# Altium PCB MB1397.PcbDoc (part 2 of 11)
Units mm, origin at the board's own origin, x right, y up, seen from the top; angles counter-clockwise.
Board outline 118.24 x 172.86 mm, 6 copper layers (Top Layer, L2_GND, L3_VCC, L4_SIG, L5_GND, Bottom Layer), stack 1.631 mm thick; 819 components, 632 nets, 2875 pads, 1523 vias.
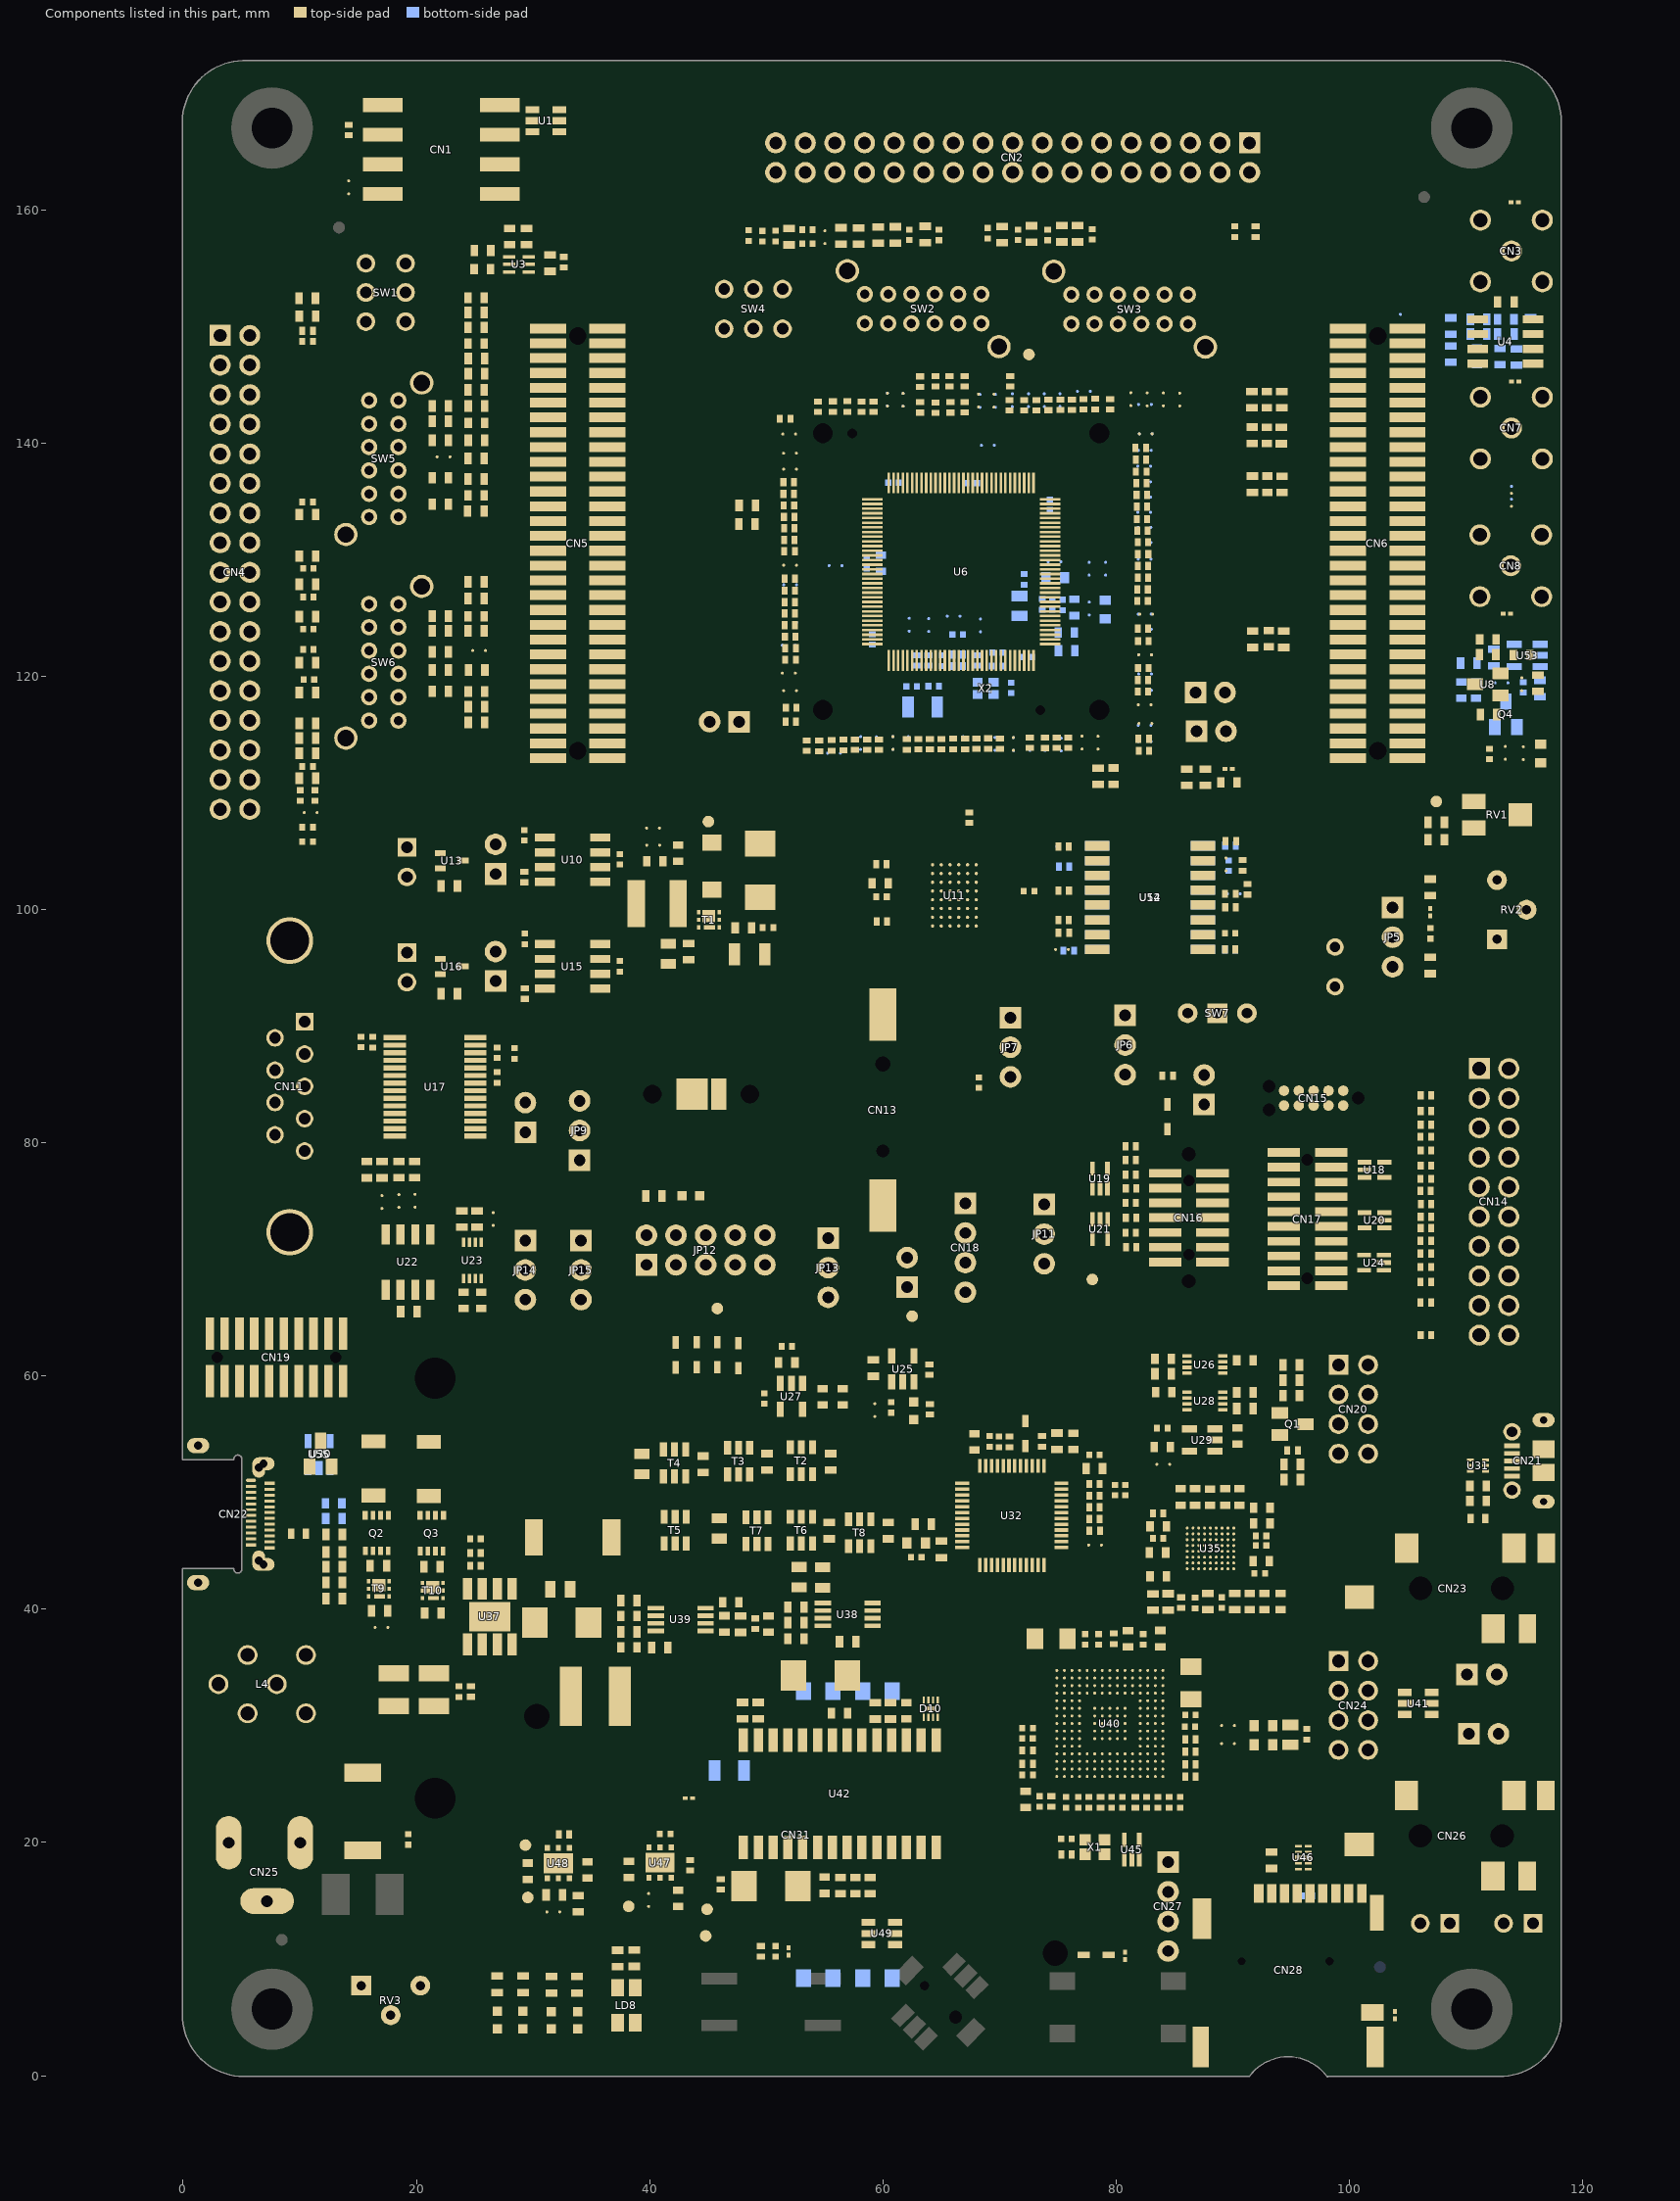
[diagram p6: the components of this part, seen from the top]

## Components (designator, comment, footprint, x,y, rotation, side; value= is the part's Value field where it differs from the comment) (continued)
HW3 "Logo" LOGO_ROHS 5.105,159.639 r0 top
HW4 "Logo" LOGO_MAIN_1 99.464,155.618 r0 top
HW5 "Logo" LOGO_CE 105.562,155.981 r0 top
HW7 "Comment" STICKER_25X9 41.176,60.325 r180 bottom
JP1 "Jumper_Header 2x1" CON_SAMTEC_TSW-102-07-G-S 46.406,116.098 r180 top
JP2 "Jumper_Header 2x1" CON_SAMTEC_TSW-102-07-G-S 26.782,104.314 r90 top
JP4 "Jumper_Header 2x1" CON_SAMTEC_TSW-102-07-G-S 26.782,95.124 r90 top
JP5 "Jumper_Header 3x1" CON_SAMTEC_TSW-103-07-F-S 103.701,97.627 r270 top
JP6 "Jumper_Header 3x1" CON_SAMTEC_TSW-103-07-F-S 80.772,88.377 r270 top
JP7 "Jumper_Header 3x1" CON_SAMTEC_TSW-103-07-F-S 70.924,88.187 r270 top
JP8 "Jumper_Header 2x1" CON_SAMTEC_TSW-102-07-G-S 87.538,84.54 r90 top
JP9 "Jumper_Header 3x1" CON_SAMTEC_TSW-103-07-F-S 33.995,81.05 r90 top
JP10 "Jumper_Header 2x1" CON_SAMTEC_TSW-102-07-G-S 29.337,82.169 r90 top
JP11 "Jumper_Header 3x1" CON_SAMTEC_TSW-103-07-F-S 73.83,72.162 r270 top
JP12 "Jumper_Header 5x2 Fitted 1-2" CON_SAMTEC_TSW-105-07-X-D 44.797,70.803 r0 top
JP13 "Jumper_Header 3x1" CON_SAMTEC_TSW-103-07-F-S 55.304,69.286 r270 top
JP14 "Jumper_Header 3x1" CON_SAMTEC_TSW-103-07-F-S 29.337,69.088 r270 top
JP15 "Jumper_Header 3x1" CON_SAMTEC_TSW-103-07-F-S 34.117,69.088 r270 top
JP16 "Jumper_Header 2x1" CON_SAMTEC_TSW-102-07-G-S 111.354,34.417 r0 top
JP17 "Jumper_Header 2x1" CON_SAMTEC_TSW-102-07-G-S 111.506,29.314 r0 top
JP18 "Jumper_Header 2x1" CON_SAMTEC_TSW-102-07-G-S 62.078,68.885 r90 top
L1 "BEAD" L0603 116.383,113.379 r90 top
L2 "Inductor" IND_POWER_CYNTEC_PSI054T 40.642,100.505 r180 top
L3 "BEAD" L0603 62.837,45.691 r180 top
L4 "BNX002-01" FIL_MURATA_BNX002-01 8.026,33.576 r180 top locked
L5 "INDUCTOR_POWER" IND_TDK_VLS6045EX-4R7M 35.331,32.537 r0 top
L6 "BEAD" L0603 92.634,30.023 r0 top
L7 "BEAD" L0603 92.634,28.385 r0 top
L8 "BEAD" L0603 74.778,128.44 r180 bottom
L9 "BEAD" L0603 79.052,125.705 r90 bottom
LD1 "LED_green" LED_0603_OSRAM_LG-Q396-PS-35_GREEN_1A2K_H0P4 26.924,4.766 r90 top
LD2 "LED_orange" LED_0603_OSRAM_LO-Q976-PS-25_ORANGE_1A2K_H0P8 29.143,4.766 r90 top
LD3 "LED_red" LED_0603_VISHAY_VLMS1300-GS08_RED_1A2K_H0P8 31.567,4.752 r90 top
LD4 "LED_blue" LED_0603_OSRAM_LB-Q39G-L2OO-35-1_BLUE_1A2K_H0P4 33.81,4.752 r90 top
LD5 "LED_white" LED_EVERLUCK_CWC12100_WHITE_1A2K 44.426,84.161 r0 top
LD6 "LED_green" LED_0603_OSRAM_LG-Q396-PS-35_GREEN_1A2K_H0P4 43.534,75.442 r0 top
LD7 "LED_red" LED_0603_VISHAY_VLMS1300-GS08_RED_1A2K_H0P8 62.637,57.028 r90 top
LD8 "LD_BICOLOR_CMS" LED_BI-GR_HSMF-A201-A00J1 38.006,6.05 r0 top
LPB1 "LPB-S01110101S" LIGHT_10MM-SQUARE-LIGHT-BAR_LUMEX_LPB-S01110101S-110945 44.416,84.149 r0 top
Q1 "BSN20" MOS_SOT23 95.123,55.88 r270 top
Q2 "STL9P3LLH6" MOS_POWERFLAT_3P3X3P3_P065 16.602,46.53 r0 top
Q3 "STL9P3LLH6" MOS_POWERFLAT_3P3X3P3_P065 21.308,46.529 r0 top
Q4 "9013-SOT23" NPN_SOT23 113.411,116.738 r180 bottom
R1 "Resistor" R0402 14.192,166.827 r90 top
R2 "Resistor" R0603 75.328,157.937 r90 top
R3 "Resistor" R0603 76.694,157.937 r270 top
R4 "Resistor" R0603 72.726,157.924 r90 top
R5 "Resistor" R0603 63.634,157.887 r270 top
R6 "Resistor" R0603 70.203,157.861 r90 top
R7 "Resistor" R0603 61.07,157.845 r270 top
R8 "Resistor" R0603 59.603,157.818 r90 top
R9 "Resistor" R0402 91.945,158.115 r270 top
R10 "Resistor" R0603 56.388,157.752 r270 top
R11 "Resistor" R0603 57.93,157.737 r90 top
R12 "Resistor" R0603 51.96,157.687 r270 top
R13 "Resistor" R0603 29.439,157.709 r270 top
R14 "Resistor" R0603 31.445,155.423 r90 top
R15 "Resistor" R0603 25.679,156.507 r0 top
R16 "Resistor" R0402 32.639,155.51 r90 top
R17 "Resistor" R0603 27.991,157.709 r270 top
R18 "Resistor" R0603 10.64,152.425 r0 top
R19 "Resistor" R0603 113.411,152.095 r0 top
R20 "Resistor" R0603 25.121,151.181 r180 top
R21 "Resistor" R0603 10.66,150.876 r180 top
R22 "Resistor" R0603 25.121,149.911 r0 top
R23 "Resistor" R0402 10.668,149.606 r0 top
R24 "Resistor" R0603 25.146,147.241 r0 top
R25 "Resistor" R0603 25.146,145.948 r180 top
R26 "Resistor" R0402 64.501,145.288 r270 top
R27 "Resistor" R0402 65.703,145.288 r90 top
R28 "Resistor" R0402 67.003,145.288 r90 top
R29 "Resistor" R0402 70.903,145.288 r90 top
R30 "Resistor" R0402 63.19,145.263 r270 top
R31 "Resistor" R0603 25.121,144.542 r180 top
R32 "Resistor" R0603 91.645,143.724 r270 top
R33 "Resistor" R0603 94.185,143.724 r270 top
R34 "Resistor" R0402 77.188,143.312 r90 top
R35 "Resistor" R0402 79.477,143.325 r90 top
R36 "Resistor" R0402 78.194,143.333 r90 top
R37 "Resistor" R0402 76.2,143.283 r90 top
R38 "Resistor" R0402 75.209,143.275 r90 top
R39 "Resistor" R0402 74.196,143.265 r90 top
R40 "Resistor" R0402 70.852,143.236 r90 top
R41 "Resistor" R0402 72.103,143.236 r90 top
R42 "Resistor" R0402 73.152,143.236 r90 top
R43 "Resistor" R0402 55.702,143.121 r90 top
R44 "Resistor" R0402 56.946,143.126 r270 top
R45 "Resistor" R0402 58.166,143.099 r270 top
R46 "Resistor" R0402 59.181,143.099 r270 top
R47 "Resistor" R0402 54.43,143.101 r270 top
R48 "Resistor" R0402 67.003,143.074 r90 top
R49 "Resistor" R0402 63.19,143.053 r270 top
R50 "Resistor" R0402 65.786,143.053 r90 top
R51 "Resistor" R0603 25.146,143.184 r180 top
R52 "Resistor" R0603 22.051,143.179 r0 top
R53 "Resistor" R0402 64.501,143.024 r90 top
R54 "Resistor" R0402 51.61,142.085 r0 top
R55 "Resistor" R0603 22.051,141.875 r0 top
R56 "Resistor" R0603 91.658,140.665 r90 top
R57 "Resistor" R0603 94.168,140.637 r90 top
R58 "Resistor" R0603 22.051,140.228 r0 top
R59 "Resistor" R0603 25.146,140.228 r0 top
R60 "Resistor" R0402 82.099,139.573 r180 top
R61 "Resistor" R0603 25.113,138.674 r0 top
R62 "Resistor" R0402 82.118,138.582 r180 top
R63 "Resistor" R0402 82.149,137.541 r180 top
R64 "Resistor" R0603 22.051,137.017 r0 top
R65 "Resistor" R0603 91.693,136.463 r90 top
R66 "Resistor" R0603 25.113,136.925 r0 top
R67 "Resistor" R0603 94.216,136.444 r90 top
R68 "Resistor" R0402 51.918,136.627 r180 top
R69 "Resistor" R0402 82.169,136.55 r180 top
R70 "Resistor" R0402 51.919,135.636 r180 top
R71 "Resistor" R0402 82.194,135.56 r180 top
R72 "Resistor" R0603 22.042,134.747 r0 top
R73 "Resistor" R0603 48.362,134.645 r180 top
R74 "Resistor" R0402 51.944,134.645 r180 top
R75 "Resistor" R0402 82.208,134.536 r180 top
R76 "Resistor" R0603 25.095,134.163 r180 top
R77 "Resistor" R0603 10.66,133.866 r0 top
R78 "Resistor" R0402 51.96,133.666 r180 top
R79 "Resistor" R0402 82.211,133.473 r180 top
R80 "Resistor" R0603 48.336,133.045 r180 top
R81 "Resistor" R0402 51.972,132.69 r180 top
R82 "Resistor" R0402 82.25,132.48 r180 top
R83 "Resistor" R0402 51.972,131.695 r180 top
R84 "Resistor" R0402 82.287,131.489 r180 top
R85 "Resistor" R0402 51.994,130.708 r180 top
R86 "Resistor" R0603 10.66,130.302 r180 top
R87 "Resistor" R0402 82.305,130.468 r0 top
R88 "Resistor" R0402 82.287,129.457 r0 top
R89 "Resistor" R0402 82.292,128.441 r0 top
R90 "Resistor" R0402 52.019,128.366 r180 top
R91 "Resistor" R0603 25.121,128.079 r0 top
R92 "Resistor" R0603 10.66,127.889 r180 top
R93 "Resistor" R0402 82.262,127.455 r0 top
R94 "Resistor" R0402 52.022,127.341 r180 top
R95 "Resistor" R0603 25.121,126.67 r0 top
R96 "Resistor" R0402 82.262,126.451 r0 top
R97 "Resistor" R0402 52.019,126.365 r180 top
R98 "Resistor" R0402 52.019,125.375 r180 top
R99 "Resistor" R0603 22.051,125.166 r0 top
R100 "Resistor" R0603 10.66,125.103 r180 top
R101 "Resistor" R0402 52.019,124.384 r180 top
R102 "Resistor" R0402 82.294,124.079 r0 top
R103 "Resistor" R0603 22.051,123.879 r0 top
R104 "Resistor" R0603 25.121,123.879 r180 top
R105 "Resistor" R0603 91.702,123.167 r270 top
R106 "Resistor" R0603 94.349,123.167 r270 top
R107 "Resistor" R0402 52.045,123.393 r180 top
R108 "Resistor" R0402 82.321,123.018 r0 top
R109 "Resistor" R0402 52.078,122.411 r0 top
R110 "Resistor" R0603 22.051,122.082 r0 top
R111 "Resistor" R0603 111.851,121.856 r180 top
R112 "Resistor" R0402 52.078,121.412 r180 top
R113 "Resistor" R0603 10.66,121.158 r0 top
R114 "Resistor" R0603 22.051,120.545 r0 top
R115 "Resistor" R0603 25.171,120.541 r180 top
R116 "Resistor" R0402 82.321,120.701 r180 top
R117 "Resistor" R0603 116.176,119.407 r90 top
R118 "Resistor" R0402 82.296,119.667 r180 top
R119 "Resistor" R0603 22.051,118.707 r0 top
R120 "Resistor" R0603 10.66,118.603 r0 top
R121 "Resistor" R0402 82.284,118.684 r180 top
R122 "Resistor" R0603 25.146,117.373 r0 top
R123 "Resistor" R0402 52.124,117.299 r0 top
R124 "Resistor" R0603 111.933,116.698 r0 top
R125 "Resistor" R0603 25.146,116.027 r0 top
R126 "Resistor" R0603 10.66,115.951 r180 top
R127 "Resistor" R0402 52.097,116.098 r180 top
R128 "Resistor" R0603 10.66,114.681 r0 top
R129 "Resistor" R0402 82.357,114.623 r180 top
R130 "Resistor" R0402 72.603,114.3 r90 top
R131 "Resistor" R0402 74.888,114.3 r90 top
R132 "Resistor" R0402 75.888,114.3 r270 top
R133 "Resistor" R0402 73.889,114.288 r90 top
R134 "Resistor" R0402 69.012,114.224 r270 top
R135 "Resistor" R0402 68.016,114.215 r270 top
R136 "Resistor" R0402 70.029,114.215 r270 top
R137 "Resistor" R0402 66.015,114.198 r270 top
R138 "Resistor" R0402 67.039,114.198 r270 top
R139 "Resistor" R0402 64.028,114.173 r270 top
R140 "Resistor" R0402 65.016,114.173 r270 top
R141 "Resistor" R0402 63.043,114.167 r90 top
R142 "Resistor" R0402 62.052,114.155 r90 top
R143 "Resistor" R0402 58.649,114.138 r90 top
R144 "Resistor" R0402 59.665,114.131 r90 top
R145 "Resistor" R0402 57.607,114.122 r90 top
R146 "Resistor" R0402 56.617,114.105 r90 top
R147 "Resistor" R0402 55.601,114.071 r90 top
R148 "Resistor" R0402 53.467,114.038 r90 top
R149 "Resistor" R0402 54.534,114.021 r90 top
R150 "Resistor" R0402 82.372,113.6 r180 top
R151 "Resistor" R0603 10.66,113.41 r180 top
R152 "Resistor" R0603 78.461,111.43 r90 top
R153 "Resistor" R0603 86.034,111.342 r90 top
R154 "Resistor" R0603 87.647,111.342 r90 top
R155 "Resistor" R0603 10.66,111.252 r0 top
R156 "Resistor" R0402 67.41,107.872 r270 top
R157 "Resistor" R0603 107.442,107.479 r180 top
R158 "Resistor" R0603 107.442,105.983 r180 top
R159 "Resistor" R0402 89.83,105.861 r180 top
R160 "Resistor" R0402 75.497,105.408 r180 top
R161 "Resistor" R0402 90.839,103.783 r90 top
R162 "Resistor" R0402 59.866,103.885 r0 top
R163 "Resistor" R0402 29.25,102.782 r90 top
R164 "Resistor" R0603 106.934,101.9 r90 top
R165 "Resistor" R0603 22.821,102.027 r0 top
R166 "Resistor" R0402 91.26,101.728 r90 top
R167 "Resistor" R0402 75.502,101.626 r180 top
R168 "Resistor" R0402 89.785,101.349 r180 top
R169 "Resistor" R0402 89.794,100.175 r180 top
R170 "Resistor" R0402 75.497,99.086 r180 top
R171 "Resistor" R0402 59.917,98.982 r180 top
R172 "Resistor" R0603 48.031,98.425 r0 top
R173 "Resistor" R0402 75.514,97.993 r180 top
R174 "PT100" PHO_SENBAN_GL55XX 98.762,95.077 r90 top
R175 "Resistor" R0805 41.6,96.197 r90 top
R176 "Resistor" R0603 43.325,96.394 r90 top
R177 "Resistor" R1206_H0P55 48.569,96.164 r180 top
R178 "Resistor" R0402 89.762,96.569 r180 top
R179 "Resistor" R0603 106.934,95.202 r90 top
R180 "Resistor" R0402 29.303,92.788 r270 top
R181 "Resistor" R0603 22.82,92.788 r0 top
R182 "Resistor" R0402 84.41,85.75 r180 top
R183 "Resistor" R0402 106.553,84.074 r180 top
R184 "Resistor" R0402 106.553,82.725 r180 top
R185 "Resistor" R0402 106.553,81.534 r180 top
R186 "Resistor" R0402 106.541,80.518 r180 top
R187 "Resistor" R0402 81.247,79.708 r180 top
R188 "Resistor" R0402 106.553,79.339 r180 top
R189 "Resistor" R0402 81.247,78.527 r0 top
R190 "Resistor" R0603 18.501,77.709 r90 top
R191 "Resistor" R0603 19.847,77.709 r270 top
R192 "Resistor" R0603 17.044,77.687 r270 top
R193 "Resistor" R0402 106.553,78.039 r180 top
R194 "Resistor" R0402 81.25,77.261 r180 top
R195 "Resistor" R0402 106.541,76.898 r0 top
R196 "Resistor" R0402 81.273,76.077 r180 top
R197 "Resistor" R0402 106.528,75.867 r0 top
R198 "Resistor" R0603 40.362,75.442 r0 top
R199 "Resistor" R0402 81.234,74.847 r180 top
R200 "Resistor" R0402 106.558,74.727 r180 top
R201 "Resistor" R0603 23.897,73.465 r90 top
R202 "Resistor" R0603 25.201,73.465 r90 top
R203 "Resistor" R0402 106.553,73.66 r0 top
R204 "Resistor" R0402 81.273,73.577 r180 top
R205 "Resistor" R0402 106.553,72.69 r0 top
R206 "Resistor" R0402 81.25,72.286 r180 top
R207 "Resistor" R0402 106.541,71.59 r180 top
R208 "Resistor" R0402 81.28,71.036 r180 top
R209 "Resistor" R0402 106.541,70.485 r180 top
R210 "Resistor" R0402 106.541,69.342 r0 top
R211 "Resistor" R0402 106.541,68.072 r180 top
R212 "Resistor" R0402 106.541,66.294 r0 top
R213 "Resistor" R0603 19.347,65.532 r180 top
R214 "Resistor" R0402 106.553,63.5 r0 top
R215 "Resistor" R0603 59.167,60.678 r270 top
R216 "Resistor" R0603 95.011,60.96 r0 top
R217 "Resistor" R0402 63.98,60.543 r90 top
R218 "Resistor" R0603 84.021,60.194 r180 top
R219 "Resistor" R0603 95.011,59.639 r180 top
R220 "Resistor" R0603 95.011,58.318 r0 top
R221 "Resistor" R0402 64.028,57.15 r270 top
R222 "Resistor" R0603 91.031,57.222 r0 top
R223 "Resistor" R0603 74.929,54.409 r90 top
R224 "Resistor" R0402 73.644,54.394 r270 top
R225 "Resistor" R0402 70.845,54.353 r90 top
R226 "Resistor" R0402 95.123,53.619 r0 top
R227 "Resistor" R0805 39.342,52.451 r270 top
R228 "Resistor" R0603 55.512,52.642 r90 top
R229 "Resistor" R0603 50.069,52.64 r270 top
R230 "Resistor" R0603 44.577,52.433 r270 top
R231 "Resistor" R0603 95.098,52.426 r0 top
R232 "Resistor" R0603 78.129,52.063 r180 top
R233 "Resistor" R0603 95.098,51.13 r0 top
R234 "Resistor" R0402 78.129,50.741 r0 top
R235 "Resistor" R0402 78.138,49.725 r180 top
R236 "Resistor" R0402 78.129,48.738 r0 top
R237 "Resistor" R0402 83.597,48.225 r0 top
R238 "Resistor" R0805 45.971,46.933 r90 top
R239 "Resistor" R0402 78.129,47.738 r180 top
R240 "Resistor" R0603 63.46,47.29 r180 top
R241 "Resistor" R0603 60.456,46.737 r90 top
R242 "Resistor" R0603 55.39,46.736 r270 top
R243 "Resistor" R0402 78.154,46.738 r180 top
R244 "Resistor" R0603 12.954,46.403 r180 top
R245 "Resistor" R0603 64.996,45.132 r270 top
R246 "Resistor" R0603 12.954,44.904 r180 top
R247 "Resistor" R0402 25.064,44.815 r180 top
R248 "Resistor" R0603 16.736,43.736 r180 top
R249 "Resistor" R0603 21.336,43.645 r0 top
R250 "Resistor" R0603 12.954,43.634 r180 top
R251 "Resistor" R0402 25.064,43.728 r0 top
R252 "Resistor" R0805 52.804,42.751 r90 top
R253 "Resistor" R0805 54.821,42.726 r90 top
R254 "Resistor" R0603 12.954,42.306 r180 top
R255 "Resistor" R0603 90.152,40.656 r270 top
R256 "Resistor" R0603 87.84,40.656 r270 top
R257 "Resistor" R0603 84.455,40.632 r270 top
R258 "Resistor" R0603 83.147,40.615 r270 top
R259 "Resistor" R0603 12.954,40.906 r180 top
R260 "Resistor" R0603 38.219,40.741 r0 top
R261 "Resistor" R0402 85.57,40.565 r90 top
R262 "Resistor" R0603 52.539,40.179 r180 top
R263 "Resistor" R0603 16.843,39.858 r180 top
R264 "Resistor" R0603 21.41,39.672 r180 top
R265 "Resistor" R0603 47.802,38.712 r90 top
R266 "Resistor" R0402 49.054,38.764 r270 top
R267 "Resistor" R0603 52.539,38.851 r0 top
R268 "Resistor" R0603 38.219,38.051 r180 top
R269 "Resistor" R0402 79.796,37.472 r270 top
R270 "Resistor" R0603 56.977,37.208 r180 top
R271 "Resistor" R0603 40.869,36.722 r180 top
R272 "Resistor" R0402 24.675,32.941 r90 top
R273 "Resistor" R0603 47.974,31.312 r90 top
R274 "Resistor" R0603 49.313,31.312 r90 top
R275 "Resistor" R0603 59.336,31.287 r90 top
R276 "Resistor" R0603 60.657,31.287 r270 top
R277 "Resistor" R0402 86.371,28.851 r0 top
R278 "Resistor" R0402 72.401,27.888 r0 top
R279 "Resistor" R0402 86.371,27.778 r180 top
R280 "Resistor" R0402 72.401,26.751 r0 top
R281 "Resistor" R0402 86.371,26.69 r0 top
R282 "Resistor" R0402 86.371,25.656 r0 top
R283 "Resistor" R0402 74.433,23.518 r90 top
R284 "Resistor" R0402 78.664,23.449 r90 top
R285 "Resistor" R0402 81.636,23.449 r90 top
R286 "Resistor" R0402 32.655,20.688 r180 top
R287 "Resistor" R0603 93.323,18.476 r90 top
R288 "Resistor" R0402 75.742,18.961 r0 top
R289 "Resistor" R0402 43.472,18.052 r270 top
R290 "Resistor" R0603 58.9,16.299 r270 top
R291 "Resistor" R0402 46.103,16.402 r270 top
R292 "Resistor" R0603 31.816,15.5 r180 top
R293 "Resistor" R0603 33.868,14.75 r90 top
R294 "Resistor" R0402 49.53,10.668 r90 top
R295 "Resistor" R0603 38.685,10.077 r90 top
R296 "Resistor" R0603 37.244,10.061 r90 top
R297 "Resistor" R0603 26.924,7.843 r90 top
R298 "Resistor" R0603 29.136,7.843 r90 top
R299 "Resistor" R0603 31.567,7.8 r90 top
R300 "Resistor" R0603 33.782,7.8 r90 top
R301 "Resistor" R0603 111.062,150.607 r0 bottom
R302 "Resistor" R0603 115.542,150.038 r270 bottom
R303 "Resistor" R0603 108.684,150.032 r90 bottom
R304 "Resistor" R0603 113.411,149.357 r0 bottom
R305 "Resistor" R0603 111.062,149.337 r180 bottom
R306 "Resistor" R0603 108.687,147.622 r90 bottom
R307 "Resistor" R0603 112.903,147.403 r270 bottom
R308 "Resistor" R0603 114.311,147.373 r90 bottom
R309 "Resistor" R0402 36.195,132.08 r0 bottom
R310 "Resistor" R0603 75.747,122.196 r180 bottom
R311 "Resistor" R0603 112.367,121.608 r270 bottom
R312 "Resistor" R0402 66.403,121.866 r0 bottom
R313 "Resistor" R0402 68.103,121.346 r90 bottom
R314 "Resistor" R0402 63.906,121.346 r90 bottom
R315 "Resistor" R0402 62.903,121.346 r90 bottom
R316 "Resistor" R0603 110.221,121.136 r180 bottom
R317 "Resistor" R0402 66.403,120.866 r0 bottom
R318 "Resistor" R0603 116.341,118.948 r270 bottom
R319 "Resistor" R0402 89.797,105.485 r180 bottom
R320 "Resistor" R0402 75.538,103.681 r180 bottom
R321 "Resistor" R0402 89.762,96.569 r180 bottom
R322 "Resistor" R0402 75.929,96.468 r180 bottom
R323 "Resistor" R0603 12.926,47.777 r0 bottom
RV1 "POTENTIOMETER" POT_BOURNS_3314J-1 112.649,108.129 r270 top
RV2 "POTENTIOMETER" POT_BOURNS_3386P 112.669,99.98 r90 top locked
RV3 "POTENTIOMETER" POT_BOURNS_3386P 17.798,7.714 r0 top
SB1 "SB_ON" SOLDER-BRIDGE_R0603-0R 14.192,161.872 r90 top
SB2 "SB_OFF" SOLDER-BRIDGE_R0603-0R 55.027,157.698 r270 top
SB3 "SB_ON" SOLDER-BRIDGE_R0603-0R 60.376,143.764 r270 top
SB4 "SB_ON" SOLDER-BRIDGE_R0603-0R 61.721,143.751 r270 top
SB5 "SB_ON" SOLDER-BRIDGE_R0603-0R 81.25,143.711 r90 top
SB6 "SB_ON" SOLDER-BRIDGE_R0603-0R 68.185,143.692 r270 top
SB7 "SB_ON" SOLDER-BRIDGE_R0603-0R 82.649,143.685 r90 top
SB8 "SB_ON" SOLDER-BRIDGE_R0603-0R 84.046,143.685 r90 top
SB9 "SB_ON" SOLDER-BRIDGE_R0603-0R 69.516,143.679 r270 top
SB10 "SB_OFF" SOLDER-BRIDGE_R0603-0R 85.443,143.672 r90 top
SB11 "SB_ON" SOLDER-BRIDGE_R0603-0R 82.478,140.788 r0 top
SB12 "SB_ON" SOLDER-BRIDGE_R0603-0R 51.915,140.764 r0 top
SB13 "SB_ON" SOLDER-BRIDGE_R0603-0R 51.974,139.119 r0 top
SB14 "SB_OFF" SOLDER-BRIDGE_R0603-0R 22.276,138.812 r0 top
SB15 "SB_ON" SOLDER-BRIDGE_R0603-0R 51.986,137.763 r0 top
SB16 "SB_ON" SOLDER-BRIDGE_R0603-0R 113.891,135.177 r270 top
SB17 "SB_OFF" SOLDER-BRIDGE_R0603-0R 51.993,129.515 r0 top
SB18 "SB_ON" SOLDER-BRIDGE_R0603-0R 82.525,125.324 r0 top
SB19 "SB_OFF" SOLDER-BRIDGE_R0603-0R 25.324,122.196 r0 top
SB20 "SB_ON" SOLDER-BRIDGE_R0603-0R 82.525,121.844 r180 top
SB21 "SB_ON" SOLDER-BRIDGE_R0603-0R 51.979,120.264 r180 top
SB22 "SB_OFF" SOLDER-BRIDGE_R0603-0R 114.77,119.357 r270 top
SB23 "SB_ON" SOLDER-BRIDGE_R0603-0R 51.981,118.754 r0 top
SB24 "SB_ON" SOLDER-BRIDGE_R0603-0R 82.49,117.551 r180 top
SB25 "SB_ON" SOLDER-BRIDGE_R0603-0R 82.55,115.951 r180 top
SB26 "SB_ON" SOLDER-BRIDGE_R0603-0R 77.064,114.259 r90 top
SB27 "SB_ON" SOLDER-BRIDGE_R0603-0R 78.435,114.254 r90 top
SB28 "SB_ON" SOLDER-BRIDGE_R0603-0R 60.858,114.224 r90 top
SB29 "SB_ON" SOLDER-BRIDGE_R0603-0R 71.179,114.152 r90 top
SB30 "SB_OFF" SOLDER-BRIDGE_R0603-0R 113.365,113.379 r90 top
SB31 "SB_ON" SOLDER-BRIDGE_R0603-0R 114.907,113.36 r90 top
SB32 "SB_OFF" SOLDER-BRIDGE_R0603-0R 10.885,108.312 r0 top
SB33 "SB_ON" SOLDER-BRIDGE_R0603-0R 40.342,106.977 r180 top
SB34 "SB_ON" SOLDER-BRIDGE_R0603-0R 40.35,105.518 r180 top
SB35 "SB_ON" SOLDER-BRIDGE_R0603-0R 89.418,103.912 r270 top
SB36 "SB_OFF" SOLDER-BRIDGE_R0603-0R 75.301,96.572 r0 top
SB37 "SB_OFF" SOLDER-BRIDGE_R0603-0R 19.88,74.977 r90 top
SB38 "SB_OFF" SOLDER-BRIDGE_R0603-0R 17.044,74.962 r270 top
SB39 "SB_OFF" SOLDER-BRIDGE_R0603-0R 18.501,74.957 r90 top
SB40 "SB_ON" SOLDER-BRIDGE_R0603-0R 26.579,73.512 r270 top
SB41 "SB_ON" SOLDER-BRIDGE_R0603-0R 59.306,57.116 r270 top
SB42 "SB_ON" SOLDER-BRIDGE_R0603-0R 84.083,52.433 r180 top
SB43 "SB_ON" SOLDER-BRIDGE_R0603-0R 78.14,45.502 r0 top
SB44 "SB_ON" SOLDER-BRIDGE_R0603-0R 17.048,38.439 r180 top
SB45 "SB_OFF" SOLDER-BRIDGE_R0603-0R 89.535,30.023 r0 top
SB46 "SB_ON" SOLDER-BRIDGE_R0603-0R 89.535,28.473 r0 top
SB47 "SB_ON" SOLDER-BRIDGE_R0603-0R 39.912,15.117 r270 top
SB48 "SB_ON" SOLDER-BRIDGE_R0603-0R 31.687,14.05 r0 top
SB49 "SB_OFF" SOLDER-BRIDGE_R0603-0R 104.369,150.535 r270 bottom
SB50 "SB_OFF" SOLDER-BRIDGE_R0603-0R 99.795,150.035 r180 bottom
SB51 "SB_OFF" SOLDER-BRIDGE_R0603-0R 31.285,149.811 r0 bottom
SB52 "SB_OFF" SOLDER-BRIDGE_R0603-0R 31.285,145.999 r0 bottom
SB53 "SB_OFF" SOLDER-BRIDGE_R0603-0R 60.376,143.78 r270 bottom
SB54 "SB_OFF" SOLDER-BRIDGE_R0603-0R 61.721,143.751 r270 bottom
SB55 "SB_OFF" SOLDER-BRIDGE_R0603-0R 77.27,144.424 r180 bottom
SB56 "SB_OFF" SOLDER-BRIDGE_R0603-0R 75.183,143.723 r270 bottom
SB57 "SB_OFF" SOLDER-BRIDGE_R0603-0R 73.831,143.716 r270 bottom
SB58 "SB_OFF" SOLDER-BRIDGE_R0603-0R 72.479,143.716 r270 bottom
SB59 "SB_OFF" SOLDER-BRIDGE_R0603-0R 71.096,143.716 r270 bottom
SB60 "SB_OFF" SOLDER-BRIDGE_R0603-0R 69.647,143.664 r270 bottom
SB61 "SB_OFF" SOLDER-BRIDGE_R0603-0R 68.328,143.664 r270 bottom
SB62 "SB_OFF" SOLDER-BRIDGE_R0603-0R 36.449,143.637 r0 bottom
SB63 "SB_OFF" SOLDER-BRIDGE_R0603-0R 82.514,143.307 r180 bottom
SB64 "SB_OFF" SOLDER-BRIDGE_R0603-0R 31.371,142.24 r0 bottom
SB65 "SB_OFF" SOLDER-BRIDGE_R0603-0R 104.275,141.521 r270 bottom
SB66 "SB_OFF" SOLDER-BRIDGE_R0603-0R 36.448,142.113 r0 bottom
SB67 "SB_OFF" SOLDER-BRIDGE_R0603-0R 99.792,141.145 r180 bottom
SB68 "SB_OFF" SOLDER-BRIDGE_R0603-0R 31.343,140.891 r0 bottom
SB69 "SB_OFF" SOLDER-BRIDGE_R0603-0R 82.578,140.788 r180 bottom
SB70 "SB_OFF" SOLDER-BRIDGE_R0603-0R 68.941,139.802 r0 bottom
SB71 "SB_OFF" SOLDER-BRIDGE_R0603-0R 99.865,139.649 r0 bottom
SB72 "SB_OFF" SOLDER-BRIDGE_R0603-0R 82.499,139.37 r180 bottom
SB73 "SB_OFF" SOLDER-BRIDGE_R0603-0R 82.449,138.016 r180 bottom
SB74 "SB_OFF" SOLDER-BRIDGE_R0603-0R 82.445,136.679 r180 bottom
SB75 "SB_ON" SOLDER-BRIDGE_R0603-0R 113.891,135.677 r90 bottom
SB76 "SB_OFF" SOLDER-BRIDGE_R0603-0R 82.45,135.357 r180 bottom
SB77 "SB_OFF" SOLDER-BRIDGE_R0603-0R 82.449,134.061 r180 bottom
SB78 "SB_OFF" SOLDER-BRIDGE_R0603-0R 82.467,132.766 r180 bottom
SB79 "SB_OFF" SOLDER-BRIDGE_R0603-0R 82.467,131.47 r180 bottom
SB80 "SB_OFF" SOLDER-BRIDGE_R0603-0R 105.002,130.858 r180 bottom
SB81 "SB_OFF" SOLDER-BRIDGE_R0603-0R 68.351,124.411 r270 bottom
SB82 "SB_OFF" SOLDER-BRIDGE_R0603-0R 66.107,125.146 r180 bottom
SB83 "SB_OFF" SOLDER-BRIDGE_R0603-0R 82.479,130.046 r180 bottom
SB84 "SB_ON" SOLDER-BRIDGE_R0603-0R 79.096,129.167 r90 bottom
SB85 "SB_OFF" SOLDER-BRIDGE_R0603-0R 77.673,129.167 r90 bottom
SB86 "SB_OFF" SOLDER-BRIDGE_R0603-0R 74.762,129.809 r180 bottom
SB87 "SB_OFF" SOLDER-BRIDGE_R0603-0R 63.929,124.437 r270 bottom
SB88 "SB_OFF" SOLDER-BRIDGE_R0603-0R 62.255,124.368 r90 bottom
SB89 "SB_OFF" SOLDER-BRIDGE_R0603-0R 51.997,127.838 r0 bottom
SB90 "SB_OFF" SOLDER-BRIDGE_R0603-0R 77.679,125.755 r90 bottom
SB91 "SB_OFF" SOLDER-BRIDGE_R0603-0R 82.498,125.324 r180 bottom
SB92 "SB_OFF" SOLDER-BRIDGE_R0603-0R 51.994,124.612 r0 bottom
SB93 "SB_OFF" SOLDER-BRIDGE_R0603-0R 99.955,124.536 r180 bottom
SB94 "SB_OFF" SOLDER-BRIDGE_R0603-0R 82.507,124.028 r180 bottom
SB95 "SB_OFF" SOLDER-BRIDGE_R0603-0R 104.875,123.111 r180 bottom
SB96 "SB_ON" SOLDER-BRIDGE_R0603-0R 51.972,122.657 r180 bottom
SB97 "SB_OFF" SOLDER-BRIDGE_R0603-0R 31.375,122.125 r0 bottom
SB98 "SB_OFF" SOLDER-BRIDGE_R0603-0R 99.921,121.971 r180 bottom
SB99 "SB_OFF" SOLDER-BRIDGE_R0603-0R 36.398,121.895 r0 bottom
SB100 "SB_OFF" SOLDER-BRIDGE_R0603-0R 82.522,121.841 r180 bottom
SB101 "SB_OFF" SOLDER-BRIDGE_R0603-0R 82.522,120.19 r180 bottom
SB102 "SB_OFF" SOLDER-BRIDGE_R0603-0R 112.983,119.428 r0 bottom
SB103 "SB_OFF" SOLDER-BRIDGE_R0603-0R 36.296,119.304 r0 bottom
SB104 "SB_OFF" SOLDER-BRIDGE_R0603-0R 82.522,118.793 r180 bottom
SB105 "SB_OFF" SOLDER-BRIDGE_R0603-0R 82.474,115.789 r180 bottom
SB106 "SB_OFF" SOLDER-BRIDGE_R0603-0R 104.965,115.521 r180 bottom
SB107 "SB_ON" SOLDER-BRIDGE_R0603-0R 60.858,114.224 r90 bottom
SB108 "SB_OFF" SOLDER-BRIDGE_R0603-0R 66.878,114.215 r90 bottom
SB109 "SB_OFF" SOLDER-BRIDGE_R0603-0R 62.186,114.215 r90 bottom
SB110 "SB_ON" SOLDER-BRIDGE_R0603-0R 58.09,114.213 r90 bottom
SB111 "SB_ON" SOLDER-BRIDGE_R0603-0R 59.446,114.203 r90 bottom
SB112 "SB_OFF" SOLDER-BRIDGE_R0603-0R 69.604,114.157 r90 bottom
SB113 "SB_OFF" SOLDER-BRIDGE_R0603-0R 72.603,114.15 r90 bottom
SB114 "SB_OFF" SOLDER-BRIDGE_R0603-0R 73.889,114.138 r90 bottom
SB115 "SB_OFF" SOLDER-BRIDGE_R0603-0R 71.196,114.136 r90 bottom
SB116 "SB_OFF" SOLDER-BRIDGE_R0603-0R 75.283,114.096 r90 bottom
SB117 "SB_OFF" SOLDER-BRIDGE_R0603-0R 82.489,114.387 r180 bottom
SB118 "SB_OFF" SOLDER-BRIDGE_R0603-0R 55.753,113.411 r0 bottom
SB119 "SB_ON" SOLDER-BRIDGE_R0603-0R 75.497,105.408 r180 bottom
SB120 "SB_OFF" SOLDER-BRIDGE_R0603-0R 90.135,101.349 r180 bottom
SB121 "SB_ON" SOLDER-BRIDGE_R0603-0R 7.338,63.548 r90 bottom
SB122 "SB_ON" SOLDER-BRIDGE_R0603-0R 7.62,59.881 r90 bottom
SB123 "SB_ON" SOLDER-BRIDGE_R0603-0R 55.88,129.487 r0 bottom
SW1 "SWITCH_MS-22D16" SWI_DHS-ELECTRONICS_MS-22D16_2P2T 17.367,152.907 r270 top
SW2 "SWITCH_SS42D02" SWI_DHS-ELECTRONICS_SS42D02_4P2T 63.446,151.512 r0 top
SW3 "SWITCH_SS42D02" SWI_DHS-ELECTRONICS_SS42D02_4P2T 81.146,151.472 r0 top
SW4 "SWITCH_MS-22D16" SWI_DHS-ELECTRONICS_MS-22D16_2P2T 48.889,151.492 r0 top
SW5 "SWITCH_SS42D02" SWI_DHS-ELECTRONICS_SS42D02_4P2T 17.2,138.65 r90 top
SW6 "SWITCH_SS42D02" SWI_DHS-ELECTRONICS_SS42D02_4P2T 17.201,121.202 r90 top
SW7 "SW_MECA_1K2" SWI_EAO_09-03290-01_EXTENDED_STRAIGHT_BLACK 88.666,91.107 r90 top
T1 "STL6N2VH5" MOS_POWERFLAT_2X2_P065 45.075,99.114 r270 top
T2 "STT7P2UH7" MOS_SOT23-6L 53.001,52.734 r0 top
T3 "STT7P2UH7" MOS_SOT23-6L 47.625,52.705 r0 top
T4 "STT7P2UH7" MOS_SOT23-6L 42.126,52.539 r0 top
T5 "STT7P2UH7" MOS_SOT23-6L 42.184,46.78 r0 top
T6 "STT7P2UH7" MOS_SOT23-6L 53.007,46.777 r0 top
T7 "STT7P2UH7" MOS_SOT23-6L 49.2,46.735 r0 top
T8 "STT7P2UH7" MOS_SOT23-6L 58.001,46.559 r0 top
T9 "STL6N2VH5" MOS_POWERFLAT_2X2_P065 16.789,41.758 r270 top
T10 "STL6N2VH5" MOS_POWERFLAT_2X2_P065 21.408,41.613 r270 top
TP1 "Test Point" TP_SMD_1MM 72.517,147.588 r90 top
TP2 "Test Point" TP_SMD_1MM 107.442,109.258 r180 top
TP3 "Test Point" TP_SMD_1MM 45.028,107.536 r270 top
TP4 "Test Point" TP_SMD_1MM 77.948,68.278 r270 top
TP5 "Test Point" TP_SMD_1MM 45.799,65.786 r180 top
TP6 "Test Point" TP_SMD_1MM 62.503,65.125 r270 top
TP7 "Test Point" TP_SMD_1MM 29.35,19.774 r0 top
TP8 "Test Point" TP_SMD_1MM 29.55,15.284 r0 top
TP9 "Test Point" TP_SMD_1MM 38.199,14.526 r180 top
TP10 "Test Point" TP_SMD_1MM 44.93,14.272 r270 top
TP11 "Test Point" TP_SMD_1MM 44.803,11.986 r270 top
U1 "USBLC6-2SC6" ESD_SOT23-6L 31.097,167.627 r90 top
U2 "ESD-TRANSIL-BIDIR" ESD_ST0201 114.173,160.655 r0 top
U3 "STTS751-0DP3F" ICC_UDFN6_2X2_P065 28.782,155.321 r270 top
U4 "TSH82IDT" ICC_SO8_5X4_P127 113.36,148.702 r90 top
U5 "ESD-TRANSIL-BIDIR" ESD_ST0201 114.195,145.288 r0 top
U6 "​Please validate the IC position on the socket (pin1) not mention on the datasheet. / Eric: please add pin1 outside of socket to show MCU Pin1" ICC_LQFP128_14X14_P040_SOCKET_IRONWOOD_SG-QFE-7011MF 66.703,128.966 r90 top locked
U7 "ESD-TRANSIL-BIDIR" ESD_ST0201 113.503,125.349 r180 top
U8 "TS432AILT" ICC_SOT23-3L_H1P12 111.859,119.301 r90 top
U9 "ESD-TRANSIL" ESD_ST0201 89.634,112.042 r0 top
U10 "MCP2562FD" ICC_SO8_5X4_P127 33.386,104.266 r90 top
U11 "IS61WV51216BLL-10MLI" ICC_MINI-BGA48_9X11_P075 66.124,101.21 r180 top locked
U12 "MT25QL512ABB8ESF-0SIT" ICC_SOP2-SF_16P_10P3X7P5_P127 82.904,101.014 r90 top
U13 "ESD-TRANSIL-DUAL-BIDIR" DIO_SOT323 23.024,104.185 r270 top
U14 "ESD-TRANSIL" ESD_ST0201 106.934,99.772 r90 top
U15 "MCP2562FD" ICC_SO8_5X4_P127 33.386,95.124 r90 top
U16 "ESD-TRANSIL-DUAL-BIDIR" DIO_SOT323 23.023,95.124 r270 top
U17 "ST3241EBPR" ICC_SSOP28_10P2X5P3_P065 21.59,84.788 r270 top
U18 "ESDALC6V1W5" ESD_SOT323-5L 102.137,77.676 r270 top
U19 "ESDALC6V1W5" ESD_SOT323-5L 78.606,76.927 r0 top
U20 "ESDALC6V1W5" ESD_SOT323-5L 102.141,73.358 r90 top
U21 "ESDALC6V1W5" ESD_SOT323-5L 78.613,72.596 r180 top
U22 "ST3485EBDR" ICC_SO8_5X4_P127 19.272,69.766 r0 top
U23 "SN74LVC2T45DCUT" ICC_VSSOP8_DCU_R-PDSO-G8_2X2P30_P050 24.801,69.922 r180 top
U24 "ESDALC6V1W5" ESD_SOT323-5L 102.108,69.719 r90 top
U25 "STMPS2151STR" MOS_SOT23-5L 61.703,60.606 r0 top
U26 "SN74LVC2T45DCUT" ICC_VSSOP8_DCU_R-PDSO-G8_2X2P30_P050 87.601,60.985 r270 top
U27 "LD3985M33R" REG_SOT23-5L 52.154,58.252 r180 top
U28 "SN74LVC2T45DCUT" ICC_VSSOP8_DCU_R-PDSO-G8_2X2P30_P050 87.602,57.866 r270 top
U29 "LD3985M18R" REG_SOT23-5L 87.364,54.509 r90 top
U30 "ESDAxxL" ESD_SOT23 11.783,53.34 r0 top
U31 "ECMF02-2AMX6" ESD_QFN-6L_1P7X1P5_P050 111.004,52.316 r270 top
U32 "STM32L152CCT6" ICC_LQFP48_7X7_P050 71.057,48.042 r180 top
U33 "ESD-TRANSIL" DIO_SMC_DO214-AB_1K_2A 33.401,46.162 r180 top
U34 "ESD-TRANSIL" ESD_QFN2_1P6X1_P125 111.027,47.778 r180 top
U35 "WM8994ECS/R" ICC_W-CSP-BGA72_4P511X4P023_P050 88.077,45.216 r0 top
U36 "ESD-TRANSIL" ESD_QFN1610_2N_1K_2A 9.906,46.482 r0 top
U37 "ST1S41" ICC_HSOP8-EPAD_3P90X4P90_P127 26.289,39.361 r270 top
U38 "TSZ122IST" ICC_MINISO8_3X3_P065 56.973,39.565 r270 top
U39 "TSZ122IST" ICC_MINISO8_3X3_P065 42.655,39.115 r90 top
U40 "ST-LINKV3E_SWD" ICC_UFBGA201_176+25_10X10_P065 79.455,30.203 r90 top locked
U41 "ESDA6V1BC6" ESD_SOT23-6L 105.89,31.925 r270 top
U42 "ST8024CTR" ICC_SO28_18P10X7P60_P127 56.298,24.175 r0 top
U43 "ESD-TRANSIL" DIO_SMC_DO214-AB_1K_2A 15.397,22.649 r90 top
U44 "ESD-TRANSIL" ESD_ST0201 43.355,23.8 r0 top
U45 "ESDALC6V1W5" ESD_SOT323-5L 81.336,19.386 r0 top
U46 "HSP051-4M10" ESD_UQFN-10L_2P5X1_P050 96.042,18.699 r90 top
U47 "ST1L05CPU33R" ICC_DFN6-EPAD_3X3_P095 40.892,18.277 r180 top
U48 "ST1L05BPUR" ICC_DFN6-EPAD_3X3_P095 32.166,18.224 r180 top
U49 "ESDA6V1-5SC6" ESD_SOT23-6L 59.899,12.192 r90 top
U50 "ESD-TRANSIL" ESD_ST0201 51.914,10.668 r90 top
U51 "ESD-TRANSIL" ESD_ST0201 80.767,10.27 r90 top
U52 "ESD-TRANSIL" ESD_ST0201 103.886,5.207 r90 top
U53 "TL1431ACL5T" ICC_SOT23-5L_H1P45 115.241,121.793 r270 bottom
U54 "MT25QL512ABB8ESF-0SIT" ICC_SOP2-SF_16P_10P3X7P5_P127 82.904,101.014 r270 bottom
U55 "USBLC6-2SC6" ESD_SOT23-6L 11.656,53.261 r0 bottom
X1 "OSCILLATOR_4_PINS" OSC_NDK_NZ2520SB_4P 78.163,19.606 r0 top
X2 "XTAL_4_PINS" CRY_NX2016SA_4P 68.809,118.974 r180 bottom
X3 "XTAL_2_PINS" CRY_NX3215SA_2P 63.403,117.376 r180 bottom

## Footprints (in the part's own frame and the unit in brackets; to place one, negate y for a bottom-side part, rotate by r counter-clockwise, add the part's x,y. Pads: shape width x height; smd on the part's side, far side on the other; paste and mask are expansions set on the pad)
BAT_HARWIN_S8411-45R_SMD_2P [mm] "CR1220 HOLDER"
  rect 4.5x2.3 smd mask+0.05: 1(8.2,0) 2(-8.2,0)
  round 0 hole 1.1 unplated mask+0.05: NPTH1(-3.5,0)
  round 0 hole 1.3 unplated mask+0.05: NPTH2(3.95,0)
  silkscreen extent -9.03,-7.5 9.62,7.5, body extent -8.93,-7.5 9.88,7.5, height 4.31
C0402 [mm]
  rect 0.51x0.56 smd mask+0.05: 1(-0.45,0) 2(0.45,0)
  silkscreen extent -0.72,-0.35 0.72,0.35, body extent -0.5,-0.3 0.5,0.3, height 0.4
C0603 [mm]
  rect 0.64x0.89 smd mask+0.05: 1(-0.7,0) 2(0.7,0)
  silkscreen extent -1.05,-0.55 1.02,0.55, body extent -0.9,-0.5 0.9,0.5, height 1.4
C0805 [mm]
  rect 0.9x1.4 smd mask+0.05: 1(-0.85,0) 2(0.85,0)
  silkscreen extent -1.3,-0.77 1.3,0.77, body extent -1.1,-0.7 1.1,0.7, height 1.35
C1206_H1P15 [mm]
  rect 1.4x1.78 smd mask+0.05: 1(-1.4,0) 2(1.4,0)
  silkscreen extent -2.12,-0.97 2.15,0.97, body extent -1.7,-0.9 1.7,0.9, height 1.35
C1210 [mm]
  rect 1.4x2.6 smd mask+0.05: 1(-1.4,0) 2(1.4,0)
  silkscreen extent -2.1,-1.43 2.1,1.43, body extent -1.75,-1.35 1.75,1.35, height 2.5
CON_988-JIUBABA_PHFS25-11-02-G0B115-T-1 [mm]
  rect 1.6x1.6 hole 1 mask+0.05: 1(1.27,0)
  round 1.6 hole 1 mask+0.05: 2(-1.27,0)
  silkscreen extent -2.71,-1.33 2.71,1.33, body extent -2.71,-1.33 2.71,1.33, height 8.85
CON_CARD-SOCKET_GUANG-LIAN-WEI_2480-208-503-100-RC [mm]
  rect 1.5x1.3 smd mask+0.05: C1(-12.3,-3.81) C2(-12.3,-1.27) C3(-12.3,1.27) C4(-12.3,3.81) C5(12.3,-3.81) C6(12.3,-1.27) C7(12.3,1.27) C8(12.3,3.81)
  round 0 hole 2.15 unplated mask+0.05: NPTH1(-10.16,26.67) NPTH2(10.16,-17.78)
  rect 1.75x1 smd mask+0.05: S1(-5.5,8.89) S2(-5.5,11.43)
  silkscreen extent -16.96,-24.89 14.14,31.11, body extent -16.96,-24.89 14.14,31.11, height 3.86
CON_CVILUX_CH87-20-2-V-1-00 [mm]
  rect 1.8x1.8 hole 1.2 mask+0.05: 1(-11.43,-1.27)
  round 1.8 hole 1.2 mask+0.05: 2(-11.43,1.27) 3(-8.89,-1.27) 4(-8.89,1.27) 5(-6.35,-1.27) 6(-6.35,1.27) 7(-3.81,-1.27) 8(-3.81,1.27) 9(-1.27,-1.27) 10(-1.27,1.27) 11(1.27,-1.27) 12(1.27,1.27) 13(3.81,-1.27) 14(3.81,1.27) 15(6.35,-1.27) 16(6.35,1.27) 17(8.89,-1.27) 18(8.89,1.27) 19(11.43,-1.27) 20(11.43,1.27)
  silkscreen extent -16.51,-4.55 16.51,4.55, body extent -16.51,-4.57 16.51,4.57, height 9.86
CON_DB9-MALE_TYCO_3-1634580-2 [mm]
  rect 1.5x1.5 / inner round 1.5 / far side rect 1.5x1.5 hole 1 mask+0.05: 1(-5.54,8.77)
  round 1.5 hole 1 mask+0.05: 2(-2.77,8.77) 3(0,8.77) 4(2.77,8.77) 5(5.54,8.77) 6(-4.155,6.23) 7(-1.385,6.23) 8(1.385,6.23) 9(4.155,6.23)
  round 4 hole 3.3 mask+0.05: MT1(-12.5,7.5) MT2(12.5,7.5)
  silkscreen extent -15.5,-10.3 15.5,10.6, body extent -15.5,-10.3 15.5,10.6, height 13.8
CON_DC-POWER-SOCKET_CLIFF_FC68149_DC10B [mm]
  oval 2.2x4.6 hole 1 slot 3.5 at 90 deg mask+0.05: 1(-13.55,0) 3(-7.4,0)
  oval 4.6x2.2 hole 1 slot 3.5 at 0 deg mask+0.05: 2(-10.7,5)
  silkscreen extent -14.2,-4.6 0,4.6, body extent -14.3,-4.6 0.2,5.27, height 11
CON_JACK-RIGHT-ANGLE_YJ-ELECTRONIC_SMB-ZJWE-3 [mm]
  round 1.8 hole 1.2 mask+0.05: 1(0,0) 2(-2.65,2.65) 3(2.65,2.65) 4(2.65,-2.65) 5(-2.65,-2.65)
  silkscreen extent -3.5,-3.5 10.7,3.5, body extent -3.5,-3.5 10.7,3.5, height 9
CON_MICROSD_YAMAICHI_PJS008-2003-1 [mm] "WITH POSITIONNING PINS"
  rect 1.6x0.8 smd paste+0 mask+0.05: 1(-15.6,-2.525) 2(-15.6,-1.425) 3(-15.6,-0.325) 4(-15.6,0.775) 5(-15.6,1.875) 6(-15.6,2.975) 7(-15.6,4.075) 8(-15.6,5.175) 9(-15.6,6.325)
  rect 1.4x1.95 smd paste+0 mask+0.05: 10(-5.4,7.225)
  rect 3.5x1.5 smd paste+0 mask+0.05: 11(-2.45,7.45)
  rect 3.5x1.4 smd paste+0 mask+0.05: 12(-2.45,-7.5)
  rect 3.5x1.6 smd paste+0 mask+0.05: 13(-13.45,-7.4)
  rect 3.1x1.2 smd paste+0 mask+0.05: 14(-13.95,7.6)
  round 0 hole 0.65 unplated mask+0.05: NPTH1(-9.8,-4)
  round 0 hole 0.7 unplated mask+0.05: NPTH2(-9.8,3.55)
  silkscreen extent -15.32,-7.25 5.65,7.25, body extent -15.04,-7.18 -0.84,7.42, height 2
CON_PHONE-JACK-3P5_HY_PJ3028B [mm]
  rect 1.5x2.5 smd mask+0.05: 2(1.25,-3.45) 7(2.85,3.45)
  rect 2x2.5 smd mask+0.05: 3(4,-3.45) 4(5.8,3.45) 6(13.2,-3.45)
  rect 2.5x2 smd mask+0.05: 5(17.25,0.75)
  round 0.5 hole 2 unplated mask+0.1: MT1(5,0) MT2(12,0)
  Multi-Layer keep-out circle w0.01: c12,0 r1.25
  Multi-Layer keep-out circle w0.01: c5,0 r1.25
  silkscreen extent -0.9,-3.7 16,3, body extent -0.9,-3 16,3, height 5
CON_SAMTEC_FTR-130-53-L-D-LC [mm]
  rect 0.85x3.1 smd mask+0.05: 1(-18.415,-2.55) 2(-18.415,2.55) 3(-17.145,-2.55) 4(-17.145,2.55) 5(-15.875,-2.55) 6(-15.875,2.55) 7(-14.605,-2.55) 8(-14.605,2.55) 9(-13.335,-2.55) 10(-13.335,2.55) 11(-12.065,-2.55) 12(-12.065,2.55) 13(-10.795,-2.55) 14(-10.795,2.55) 15(-9.525,-2.55) 16(-9.525,2.55) 17(-8.255,-2.55) 18(-8.255,2.55) 19(-6.985,-2.55) 20(-6.985,2.55) 21(-5.715,-2.55) 22(-5.715,2.55) 23(-4.445,-2.55) 24(-4.445,2.55) 25(-3.175,-2.55) 26(-3.175,2.55) 27(-1.905,-2.55) 28(-1.905,2.55) 29(-0.635,-2.55) 30(-0.635,2.55) 31(0.635,-2.55) 32(0.635,2.55) 33(1.905,-2.55) 34(1.905,2.55) 35(3.175,-2.55) 36(3.175,2.55) 37(4.445,-2.55) 38(4.445,2.55) 39(5.715,-2.55) 40(5.715,2.55) 41(6.985,-2.55) 42(6.985,2.55) 43(8.255,-2.55) 44(8.255,2.55) 45(9.525,-2.55) 46(9.525,2.55) 47(10.795,-2.55) 48(10.795,2.55) 49(12.065,-2.55) 50(12.065,2.55) 51(13.335,-2.55) 52(13.335,2.55) 53(14.605,-2.55) 54(14.605,2.55) 55(15.875,-2.55) 56(15.875,2.55) 57(17.145,-2.55) 58(17.145,2.55) 59(18.415,-2.55) 60(18.415,2.55)
  round 0 hole 1.5 unplated mask+0.05: NPTH1(-17.78,0) NPTH2(17.78,0)
  silkscreen extent -19.05,-2.05 19.05,2.05, body extent -19.05,-3.76 19.05,3.76, height 11.05
CON_SAMTEC_FTSH-110-01-L-DV-A [mm] "MCD-XXXXX"
  round 0 hole 1 unplated mask+0.05: 0(-5.08,0) 0(5.08,0)
  rect 0.74x2.79 smd mask+0.05: 1(-5.715,-2.035) 2(-5.715,2.035) 3(-4.445,-2.035) 4(-4.445,2.035) 5(-3.175,-2.035) 6(-3.175,2.035) 7(-1.905,-2.035) 8(-1.905,2.035) 9(-0.635,-2.035) 10(-0.635,2.035) 11(0.635,-2.035) 12(0.635,2.035) 13(1.905,-2.035) 14(1.905,2.035) 15(3.175,-2.035) 16(3.175,2.035) 17(4.445,-2.035) 18(4.445,2.035) 19(5.715,-2.035) 20(5.715,2.035)
  silkscreen extent -6.35,-1.71 6.35,1.71, body extent -6.35,-2.92 6.35,2.92, height 5.97
CON_SAMTEC_SSM-104-L-DH [mm]
  rect 1.2x3.4 smd mask+0.05: 1(3.81,-5) 2(3.81,5) 3(1.27,-5) 4(1.27,5) 5(-1.27,-5) 6(-1.27,5) 7(-3.81,-5) 8(-3.81,5)
  silkscreen extent -5.08,-4.06 5.08,4.06, body extent -5.06,-5.46 5.1,5.46, height 5.92
CON_SAMTEC_TST-117-01-T-D [mm]
  rect 1.8x1.8 hole 1.1 mask+0.05: 1(-20.32,-1.27)
  round 1.8 hole 1.1 mask+0.05: 2(-20.32,1.27) 3(-17.78,-1.27) 4(-17.78,1.27) 5(-15.24,-1.27) 6(-15.24,1.27) 7(-12.7,-1.27) 8(-12.7,1.27) 9(-10.16,-1.27) 10(-10.16,1.27) 11(-7.62,-1.27) 12(-7.62,1.27) 13(-5.08,-1.27) 14(-5.08,1.27) 15(-2.54,-1.27) 16(-2.54,1.27) 17(0,-1.27) 18(0,1.27) 19(2.54,-1.27) 20(2.54,1.27) 21(5.08,-1.27) 22(5.08,1.27) 23(7.62,-1.27) 24(7.62,1.27) 25(10.16,-1.27) 26(10.16,1.27) 27(12.7,-1.27) 28(12.7,1.27) 29(15.24,-1.27) 30(15.24,1.27) 31(17.78,-1.27) 32(17.78,1.27) 33(20.32,-1.27) 34(20.32,1.27)
  silkscreen extent -25.4,-4.83 25.4,4.83, body extent -25.4,-4.83 25.4,4.83, height 9.27
CON_SAMTEC_TSW-102-07-G-S [mm]
  rect 1.85x1.85 / inner round 1.85 / far side rect 1.85x1.85 hole 1 mask+0.05: 1(-1.27,0)
  round 1.85 hole 1 mask+0.05: 2(1.27,0)
  silkscreen extent -2.58,-1.3 2.58,1.3, body extent -2.67,-1.3 2.58,1.3, height 8.38
CON_SAMTEC_TSW-103-07-F-S [mm]
  rect 1.85x1.85 / inner round 1.85 / far side rect 1.85x1.85 hole 1 mask+0.05: 1(-2.54,0)
  round 1.85 hole 1 mask+0.05: 2(0,0) 3(2.54,0)
  silkscreen extent -3.85,-1.3 3.85,1.3, body extent -3.91,-1.37 3.91,1.37, height 8.38
CON_SAMTEC_TSW-104-07-G-S [mm]
  rect 1.85x1.85 / inner round 1.85 / far side rect 1.85x1.85 hole 1 mask+0.05: 1(-3.81,0)
  round 1.85 hole 1 mask+0.05: 2(-1.27,0) 3(1.27,0) 4(3.81,0)
  silkscreen extent -5.12,-1.3 5.12,1.3, body extent -5.21,-1.37 5.18,1.37, height 8.38
CON_SAMTEC_TSW-105-07-X-D [mm]
  rect 1.85x1.85 / inner round 1.85 / far side rect 1.85x1.85 hole 1 mask+0.05: 1(-5.08,-1.27)
  round 1.85 hole 1 mask+0.05: 2(-5.08,1.27) 3(-2.54,-1.27) 4(-2.54,1.27) 5(0,-1.27) 6(0,1.27) 7(2.54,-1.27) 8(2.54,1.27) 9(5.08,-1.27) 10(5.08,1.27)
  silkscreen extent -6.35,-2.54 6.35,2.54, body extent -6.35,-2.54 6.35,2.55, height 8.38
CON_SOCKET-LCD_LYCN_216208S141 [mm]
  rect 1.7x1.7 hole 1.1 mask+0.05: 1(-3.81,-1.27)
  round 1.7 hole 1.1 mask+0.05: 2(-3.81,1.27) 3(-1.27,-1.27) 4(-1.27,1.27) 5(1.27,-1.27) 6(1.27,1.27) 7(3.81,-1.27) 8(3.81,1.27)
  silkscreen extent -6.2,-3 5.18,3, body extent -5.18,-3 5.18,3, height 7
CON_STDC14_Receiver_MEDIUM_WITH_MIPI10_3D [mm] "compatible with FTSH-105-01-L-DV,-K and FTSH-107-01-L-DV,-K,-A,-P,-ES"
  round 0 hole 1.19 unplated mask+0.05: 0(-5.445,0) 0(5.445,0)
  round 0 hole 0.97 unplated mask+0.05: 0(-3.175,0) 0(3.175,0)
  rect 0.74x2.79 smd mask+0.05: 1(-3.81,-2.032) 2(-3.81,2.032) 3(-2.54,-2.032) 4(-2.54,2.032) 5(-1.27,-2.032) 6(-1.27,2.032) 7(0,-2.032) 8(0,2.032) 9(1.27,-2.032) 10(1.27,2.032) 11(2.54,-2.032) 12(2.54,2.032) 13(3.81,-2.032) 14(3.81,2.032)
  silkscreen extent -6.3,-4.38 6.3,3.6, body extent -6.3,-2.92 6.3,2.92, height 6.6
CON_TAG-C_TC2050-IDC-NL [mm]
  round 0.9 smd paste+0 mask+0.05: 1(-2.54,-0.635) 2(-1.27,-0.635) 3(0,-0.635) 4(1.27,-0.635) 5(2.54,-0.635) 6(2.54,0.635) 7(1.27,0.635) 8(0,0.635) 9(-1.27,0.635) 10(-2.54,0.635)
  round 0 hole 1.1 unplated mask+0.05: 11(-3.81,0) 12(3.81,-1.015) 13(3.81,1.015)
  Multi-Layer keep-out circle w0.01: c-3.81,0 r0.75
  Multi-Layer keep-out circle w0.01: c3.81,1.015 r0.75
  Multi-Layer keep-out circle w0.01: c3.81,-1.015 r0.75
  silkscreen extent -6.22,-3.4 6.22,3.33, body extent -6.28,-3.46 6.28,3.39, height 13
CON_USB-TYPEC_LITKCONN-TECHNOLOGY_CNG008S130R [mm] "Doc Pin 1 = B12 et Doc Pin 13 = A1. The thickness of the pcb must be 0.8mm"
  rect 0.3x0.85 smd mask+0.05: A1(-2.645,7.58) A12(2.895,7.58) B1(2.645,5.98)
  rect 0.25x0.85 smd mask+0.05: A2(-2.125,7.58) A3(-1.625,7.58) A4(-1.125,7.58) A5(-0.625,7.58) A6(-0.125,7.58) A7(0.375,7.58) A8(0.875,7.58) A9(1.375,7.58) A10(1.875,7.58) A11(2.375,7.58) B2(2.125,5.98) B3(1.625,5.98) B4(1.125,5.98) B5(0.625,5.98) B6(0.125,5.98) B7(-0.375,5.98) B8(-0.875,5.98) B9(-1.375,5.98) B10(-1.875,5.98) B11(-2.375,5.98)
  oval 0.3x0.85 smd mask+0.05: B12(-2.895,5.98)
  oval 1.3x1.9 hole 0.7 slot 1.3 at 90 deg mask+0.05: PTH1(-5.875,1.45) PTH2(5.875,1.45)
  oval 1.1x1.9 hole 0.7 slot 1.5 at 90 deg mask+0.05: PTH3(-4.32,7.05) PTH5(4.32,7.05)
  oval 1.75x1.1 hole 0.7 slot 1.35 at 0 deg mask+0.05: PTH4(-3.995,6.65) PTH6(3.995,6.65)
  silkscreen extent -5.18,0 5.18,8.75, body extent -5.97,0 5.97,8.75, height 2.33
CON_USBMICROB_MOLEX_105017-0001_H2P90 [mm]
  rect 0.4x1.35 smd mask+0.05: 1(-1.3,4.15) 2(-0.65,4.15) 3(0,4.15) 4(0.65,4.15) 5(1.3,4.15)
  round 1.5 hole 0.9 mask+0.05: 6(-2.5,4.15) 7(2.5,4.15)
  oval 1.2x1.9 hole 0.6 slot 1.3 at 90 deg mask+0.05: 8(3.5,1.45) 9(-3.5,1.45)
  rect 1.5x1.9 smd mask+0.05: 10(-1,1.45) 11(1,1.45)
  Top Layer region: 2.3,2.4 3.5,2.4 3.5,0.5 2.3,0.5 2.3,2.4
  Top Layer region: -3.5,2.4 -2.3,2.4 -2.3,0.5 -3.5,0.5 -3.5,2.4
  silkscreen extent -4,-0.7 4,4.6, body extent -4.1,-1.15 4.1,4.66, height 2.9
CPOL_TAJ-C_2312_H2P6 [mm]
  rect 2.2x2.6 smd mask+0.05: 1(-2.3,0) 2(2.3,0)
  silkscreen extent -3.6,-1.85 3.1,1.85, body extent -3.1,-1.7 3.1,1.7, height 2.8
CRY_NX2016SA_4P [mm]
  rect 0.85x0.75 smd mask+0.05: 1(-0.675,-0.525) 2(0.675,-0.525) 3(0.675,0.525) 4(-0.675,0.525)
  silkscreen extent -1.22,-1.02 1.05,0.85, body extent -1.05,-0.85 1.05,0.85, height 0.7
CRY_NX3215SA_2P [mm]
  rect 1x1.8 smd mask+0.05: 1(-1.25,0) 2(1.25,0)
  silkscreen extent -0.63,-0.8 0.63,0.8, body extent -1.65,-0.8 1.65,0.8, height 0.9
DIO_SMA_1A_2K [mm]
  rect 1.4x1.64 smd mask+0.05: 1(2.015,0) 2(-2.015,0)
  silkscreen extent -2.3,-1.45 2.3,1.45, body extent -2.75,-1.45 2.75,1.45, height 2.7
DIO_SMB-FLAT_1A_2K [mm]
  rect 1.2x2.07 smd mask+0.05: 1(2.32,0) 2(-2.32,0)
  silkscreen extent -2.3,-2 2.3,2, body extent -2.3,-2 2.3,2, height 1.11
DIO_SMC_DO214-AB_1K_2A [mm]
  rect 1.54x3.14 smd mask+0.05: 1(-3.325,0) 2(3.325,0)
  silkscreen extent -3.6,-3.15 3.6,3.15, body extent -4.06,-3.15 4.07,3.15, height 2.66
DIO_SOD323 [mm]
  rect 1.06x0.54 smd mask+0.05: 1(-1.07,0) 2(1.07,0)
  silkscreen extent -0.9,-0.72 0.9,0.72, body extent -1.3,-0.78 1.3,0.78, height 1.17
DIO_SOT323 [mm]
  rect 0.5x0.95 smd mask+0.05: 1(-0.65,-0.975) 2(0.65,-0.975) 3(0,0.975)
  silkscreen extent -1.15,-0.67 1.15,0.67, body extent -1.15,-1.12 1.15,1.12, height 1.1
ESD_QFN2_1P6X1_P125 [mm]
  rect 0.55x0.8 smd mask+0.05: 1(-0.625,0) 2(0.625,0)
  silkscreen extent -1,-0.55 0.85,0.55, body extent -0.85,-0.55 0.85,0.55, height 0.61
ESD_QFN1610_2N_1K_2A [mm] "DFN, 2-Leads, Body 1.60x1.00mm"
  rect 0.55x0.9 smd mask+0.05: 1(-0.625,0) 2(0.625,0)
  silkscreen extent -1.02,-0.58 0.85,0.58, body extent -0.85,-0.55 0.85,0.55, height 0.6
ESD_QFN-6L_1P7X1P5_P050 [mm]
  rect 0.25x0.6 smd mask+0.05: 1(-0.5,-0.65) 2(0,-0.65) 3(0.5,-0.65) 4(0.5,0.65) 5(0,0.65) 6(-0.5,0.65)
  silkscreen extent -0.9,-0.8 0.9,0.8, body extent -0.9,-0.8 0.9,0.8, height 0.56
ESD_SOT23 [mm]
  rect 1x1.4 smd mask+0.05: 1(-0.95,-1.1) 2(0.95,-1.1) 3(0,1.1)
  silkscreen extent -1.63,-0.82 1.63,0.82, body extent -1.56,-1.5 1.56,1.5, height 1.4
ESD_SOT23-6L [mm]
  rect 0.6x1.2 smd mask+0.05: 1(-0.95,-1.15) 2(0,-1.15) 3(0.95,-1.15) 4(0.95,1.15) 5(0,1.15) 6(-0.95,1.15)
  silkscreen extent -1.53,-0.87 1.53,0.87, body extent -1.52,-1.5 1.52,1.5, height 1.45
ESD_SOT323-5L [mm]
  rect 0.4x1.2 smd mask+0.05: 1(-0.65,-0.85) 2(0,-0.85) 3(0.65,-0.85) 4(0.65,0.85) 5(-0.65,0.85)
  silkscreen extent -1.22,-1.21 1.22,0.77, body extent -1.15,-1.05 1.15,1.05, height 1.1
ESD_ST0201 [mm]
  rect 0.425x0.33 smd mask+0.05: 1(-0.312,0) 2(0.312,0)
  silkscreen extent -0.55,-0.3 0.33,0.3, body extent -0.34,-0.18 0.34,0.18, height 0.34
ESD_UQFN8-EPAD_1P7X1P5_P040 [mm]
  rect 0.2x0.6 smd mask+0.05: 1(-0.6,-0.75) 2(-0.2,-0.75) 3(0.2,-0.75) 4(0.6,-0.75) 5(0.6,0.75) 6(0.2,0.75) 7(-0.2,0.75) 8(-0.6,0.75)
  rect 1x0.4 smd mask+0.05: 9(0,0)
  silkscreen extent -1.07,-1.12 0.85,0.75, body extent -0.85,-0.75 0.85,0.75, height 0.61
ESD_UQFN-10L_2P5X1_P050 [mm]
  rect 0.2x0.58 smd mask+0.05: 1(-1,-0.41) 2(-0.5,-0.41) 4(0.5,-0.41) 5(1,-0.41) 6(1,0.41) 7(0.5,0.41) 9(-0.5,0.41) 10(-1,0.41)
  rect 0.4x0.58 smd mask+0.05: 3(0,-0.41) 8(0,0.41)
  silkscreen extent -1.38,-0.63 1.38,0.63, body extent -1.3,-0.55 1.3,0.55, height 0.51
FIL_MURATA_BNX002-01 [mm]
  round 1.7 hole 1.2 mask+0.05: 1(2.5,2.5) 2(2.5,-2.5) 3(-2.5,2.5) 4(-2.5,-2.5) 5(0,0) 6(5,0)
  silkscreen extent -6.24,-5.75 6.26,5.75, body extent -6.25,-5.75 6.25,5.75, height 13
ICC_DFN6-EPAD_3X3_P095 [mm]
  rect 0.45x0.5 smd mask+0.05: 1(-0.95,-1.3) 2(0,-1.3) 3(0.95,-1.3) 4(0.95,1.3) 5(0,1.3) 6(-0.95,1.3)
  rect 2.5x1.7 smd mask+0.05: EP(0,0)
  silkscreen extent -1.55,-1.55 1.55,1.55, body extent -1.55,-1.55 1.55,1.55, height 1
ICC_HSOP8-EPAD_3P90X4P90_P127 [mm]
  rect 1.85x0.8 smd mask+0.05: 1(-2.375,1.905) 2(-2.375,0.635) 3(-2.375,-0.635) 4(-2.375,-1.905) 5(2.375,-1.905) 6(2.375,-0.635) 7(2.375,0.635) 8(2.375,1.905)
  rect 2.5x3.5 smd mask+0.05: 9(0,0)
  silkscreen extent -2.5,-2.5 2,2.7, body extent -3.1,-2.5 3.1,2.5, height 1.75
ICC_LQFP48_7X7_P050 [mm]
  rect 0.3x1.2 smd mask+0.05: 1(-2.75,-4.25) 2(-2.25,-4.25) 3(-1.75,-4.25) 4(-1.25,-4.25) 5(-0.75,-4.25) 6(-0.25,-4.25) 7(0.25,-4.25) 8(0.75,-4.25) 9(1.25,-4.25) 10(1.75,-4.25) 11(2.25,-4.25) 12(2.75,-4.25) 25(2.75,4.25) 26(2.25,4.25) 27(1.75,4.25) 28(1.25,4.25) 29(0.75,4.25) 30(0.25,4.25) 31(-0.25,4.25) 32(-0.75,4.25) 33(-1.25,4.25) 34(-1.75,4.25) 35(-2.25,4.25) 36(-2.75,4.25)
  rect 1.2x0.3 smd mask+0.05: 13(4.25,-2.75) 14(4.25,-2.25) 15(4.25,-1.75) 16(4.25,-1.25) 17(4.25,-0.75) 18(4.25,-0.25) 19(4.25,0.25) 20(4.25,0.75) 21(4.25,1.25) 22(4.25,1.75) 23(4.25,2.25) 24(4.25,2.75) 37(-4.25,2.75) 38(-4.25,2.25) 39(-4.25,1.75) 40(-4.25,1.25) 41(-4.25,0.75) 42(-4.25,0.25) 43(-4.25,-0.25) 44(-4.25,-0.75) 45(-4.25,-1.25) 46(-4.25,-1.75) 47(-4.25,-2.25) 48(-4.25,-2.75)
  silkscreen extent -3.52,-3.52 3.52,3.52, body extent -4.5,-4.5 4.5,4.5, height 1.6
